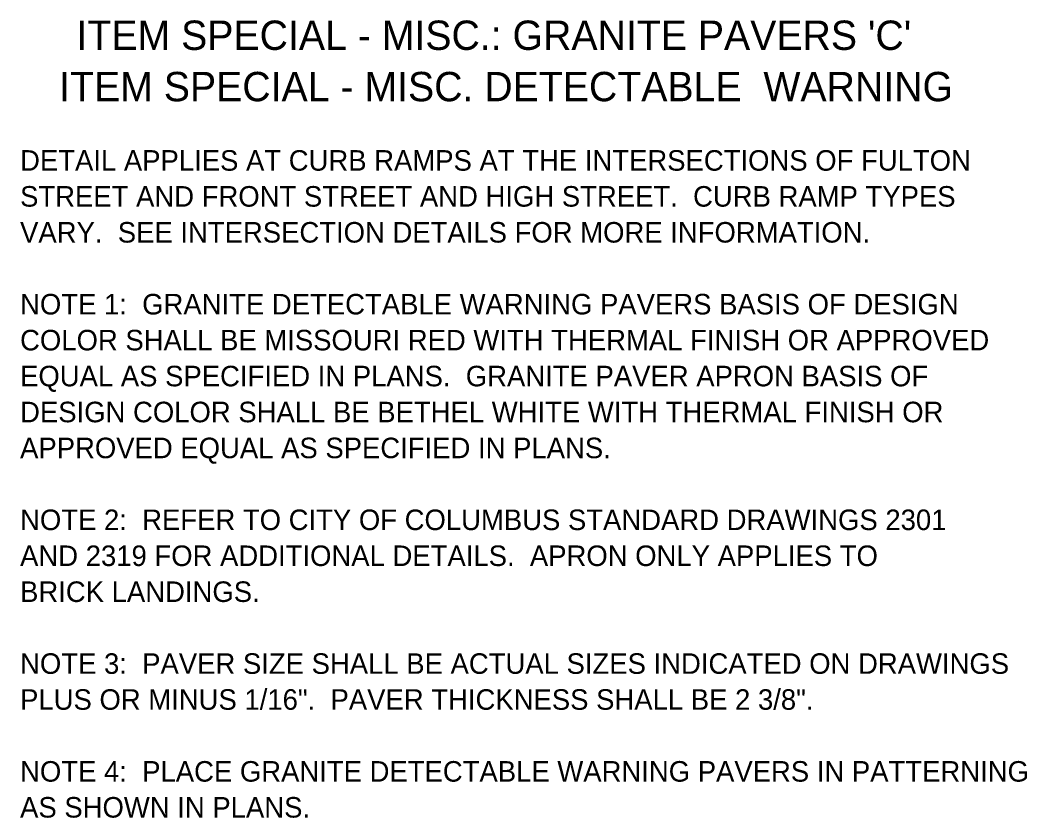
# Model space of a CAD drawing. Extents: x -848 to 1, y -1131 to -115.
# Drawn here: x -362.6 to -294, y -852.6 to -798.3 of the extents above; entities that cross this region are included whole.
import ezdxf

# ---------------------------------------------------------------- set-up
doc = ezdxf.new("R2010")
doc.units = 0
doc.layers.add('SH_Text', color=7, linetype='Continuous')

msp = doc.modelspace()

# ---------------------------------------------------------------- texts
at = {"layer": 'SH_Text'}
for s, height, p in [("ITEM SPECIAL - MISC.: GRANITE PAVERS 'C'", 2, (-358.73, -800.286)), ('ITEM SPECIAL - MISC. DETECTABLE  WARNING', 2, (-359.911, -803.786)), ('DETAIL APPLIES AT CURB RAMPS AT THE INTERSECTIONS OF FULTON ', 1.4, (-362.574, -808.521)), ('STREET AND FRONT STREET AND HIGH STREET.  CURB RAMP TYPES ', 1.4, (-362.574, -810.971)), ('VARY.  SEE INTERSECTION DETAILS FOR MORE INFORMATION.', 1.4, (-362.574, -813.421)), ('NOTE 1:  GRANITE DETECTABLE WARNING PAVERS BASIS OF DESIGN ', 1.4, (-362.574, -818.321)), ('COLOR SHALL BE MISSOURI RED WITH THERMAL FINISH OR APPROVED', 1.4, (-362.574, -820.771)), ('EQUAL AS SPECIFIED IN PLANS.  GRANITE PAVER APRON BASIS OF', 1.4, (-362.574, -823.221)), ('DESIGN COLOR SHALL BE BETHEL WHITE WITH THERMAL FINISH OR ', 1.4, (-362.574, -825.671)), ('APPROVED EQUAL AS SPECIFIED IN PLANS.', 1.4, (-362.574, -828.121)), ('NOTE 2:  REFER TO CITY OF COLUMBUS STANDARD DRAWINGS 2301', 1.4, (-362.574, -833.021)), ('AND 2319 FOR ADDITIONAL DETAILS.  APRON ONLY APPLIES TO ', 1.4, (-362.574, -835.471)), ('BRICK LANDINGS.', 1.4, (-362.574, -837.921)), ('NOTE 3:  PAVER SIZE SHALL BE ACTUAL SIZES INDICATED ON DRAWINGS ', 1.4, (-362.574, -842.821)), ('PLUS OR MINUS 1/16".  PAVER THICKNESS SHALL BE 2 3/8".', 1.4, (-362.574, -845.271)), ('NOTE 4:  PLACE GRANITE DETECTABLE WARNING PAVERS IN PATTERNING ', 1.4, (-362.574, -850.171)), ('AS SHOWN IN PLANS.', 1.4, (-362.574, -852.621))]:
    msp.add_text(s, height=height, dxfattribs=at).set_placement(p)

doc.saveas('drawing.dxf')
